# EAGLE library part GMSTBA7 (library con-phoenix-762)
PHOENIX
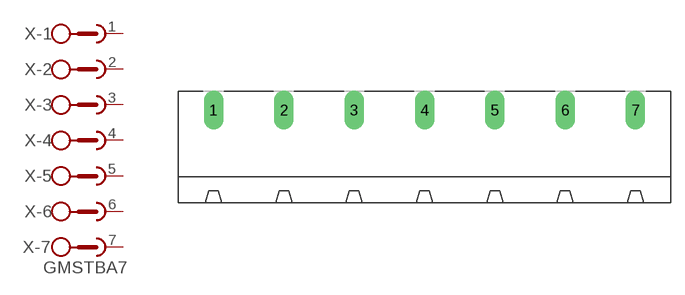
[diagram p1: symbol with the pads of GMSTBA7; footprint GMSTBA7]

Designator prefix X; gates -1=SKB -2=SKB -3=SKB -4=SKB -5=SKB -6=SKB -7=SKBV

## GMSTBA7 (OC_FARNELL: unknown; OC_NEWARK: unknown)  [GMSTBA7]
1  -1:1  pas
2  -2:1  pas
3  -3:1  pas
4  -4:1  pas
5  -5:1  pas
6  -6:1  pas
7  -7:1  pas

## Footprint GMSTBA7 (pad centres in mm)
PHOENIX
drill 1.397 long: 1 -22.86,5.08; 2 -15.24,5.08; 3 -7.62,5.08; 4 0,5.08; 5 7.62,5.08; 6 15.24,5.08; 7 22.86,5.08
